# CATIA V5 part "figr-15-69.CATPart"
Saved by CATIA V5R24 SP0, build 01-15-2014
Part number: Part1
Bounding box of the stored display mesh (mm): x -110.541 to 53, y 0 to 2, z -29.652 to 29.652
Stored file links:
  D:\KAVITA\CATIA V5-6R2014 Project_ Kavita\CATIA V5-6R2014_partfiles\Partfiles\c15_catia_v5-6r2014_prt\figr-15-69.CATPart
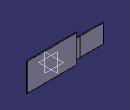
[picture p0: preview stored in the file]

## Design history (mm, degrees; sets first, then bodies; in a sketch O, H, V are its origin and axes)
SheetMetalParameters1: Thickness 2, BendRadius 4, KFactor 0.400515 {= log(min(100,max(20*SheetMetalParameters1.BendRadius,SheetMetalParameters1.Thickness)/SheetMetalParameters1.Thickness))/log(100)/2}, ReliefRadialLength 1, ReliefAxialLength 2, MinimumBendRadius 0
Body1 (main body)
  Sketch1 on zx-plane, origin (0, 0, 0), H (-1, 0, 0), V (0, 0, 1)
    line L1 (53, 29.6521) -> (53, -29.6521)
    line L2 (53, -29.6521) -> (-53, -29.6521)
    line L3 (-53, -29.6521) -> (-53, 29.6521)
    line L4 (-53, 29.6521) -> (53, 29.6521)
    vertical: L1 V, L3 V
    horizontal: L2 H, L4 H
    equidistance: L1 L3 O, L2 L4 O
  Wall1: Thickness 2, Profile Sketch1, OffsetValue 0
  Plane1: type Offset, RefPlane face of Wall1, Offset 10
  Plane2: type Offset, RefPlane face of Wall1, Offset 10
  Flange1: Angle 90, Length 50, Radius 4 {= SheetMetalParameters1.BendRadius}, Guide edge [face of Wall1 | face of Wall1], Limit1 Plane1, Limit2 Plane2, KFacteur 0.400515 {= log(min(100,max(20*Flange1.Radius,SheetMetalParameters1.Thickness)/SheetMetalParameters1.Thickness))/log(100)/2}
  Unfold1: FoldUnfold_Angles 90, FoldUnfold_FoldUnfoldFaces face of Flange1, FoldUnfold_ReferenceFaces face of Wall1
